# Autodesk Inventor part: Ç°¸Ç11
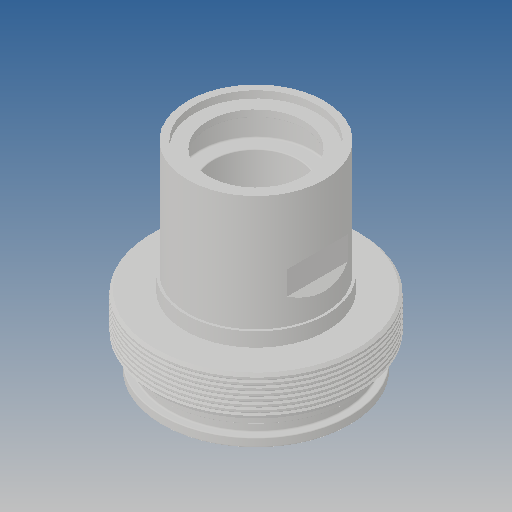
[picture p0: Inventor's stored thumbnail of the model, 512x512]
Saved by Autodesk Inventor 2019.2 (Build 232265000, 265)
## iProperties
Created: 2013-09
Part Number: Ç°¸Ç11
Material: Ogólny
Document SubType Name: Modeling
Designer: CADENGINEERING4
Density: 1 g/cm^3
Appearance: Domyślna
Author: CADENGINEERING4
Revision Number: ÈÎºÎ
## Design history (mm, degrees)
feature "À­Éì1"
node "Bryła1"
